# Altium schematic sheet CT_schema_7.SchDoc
size 259 x 245 mm
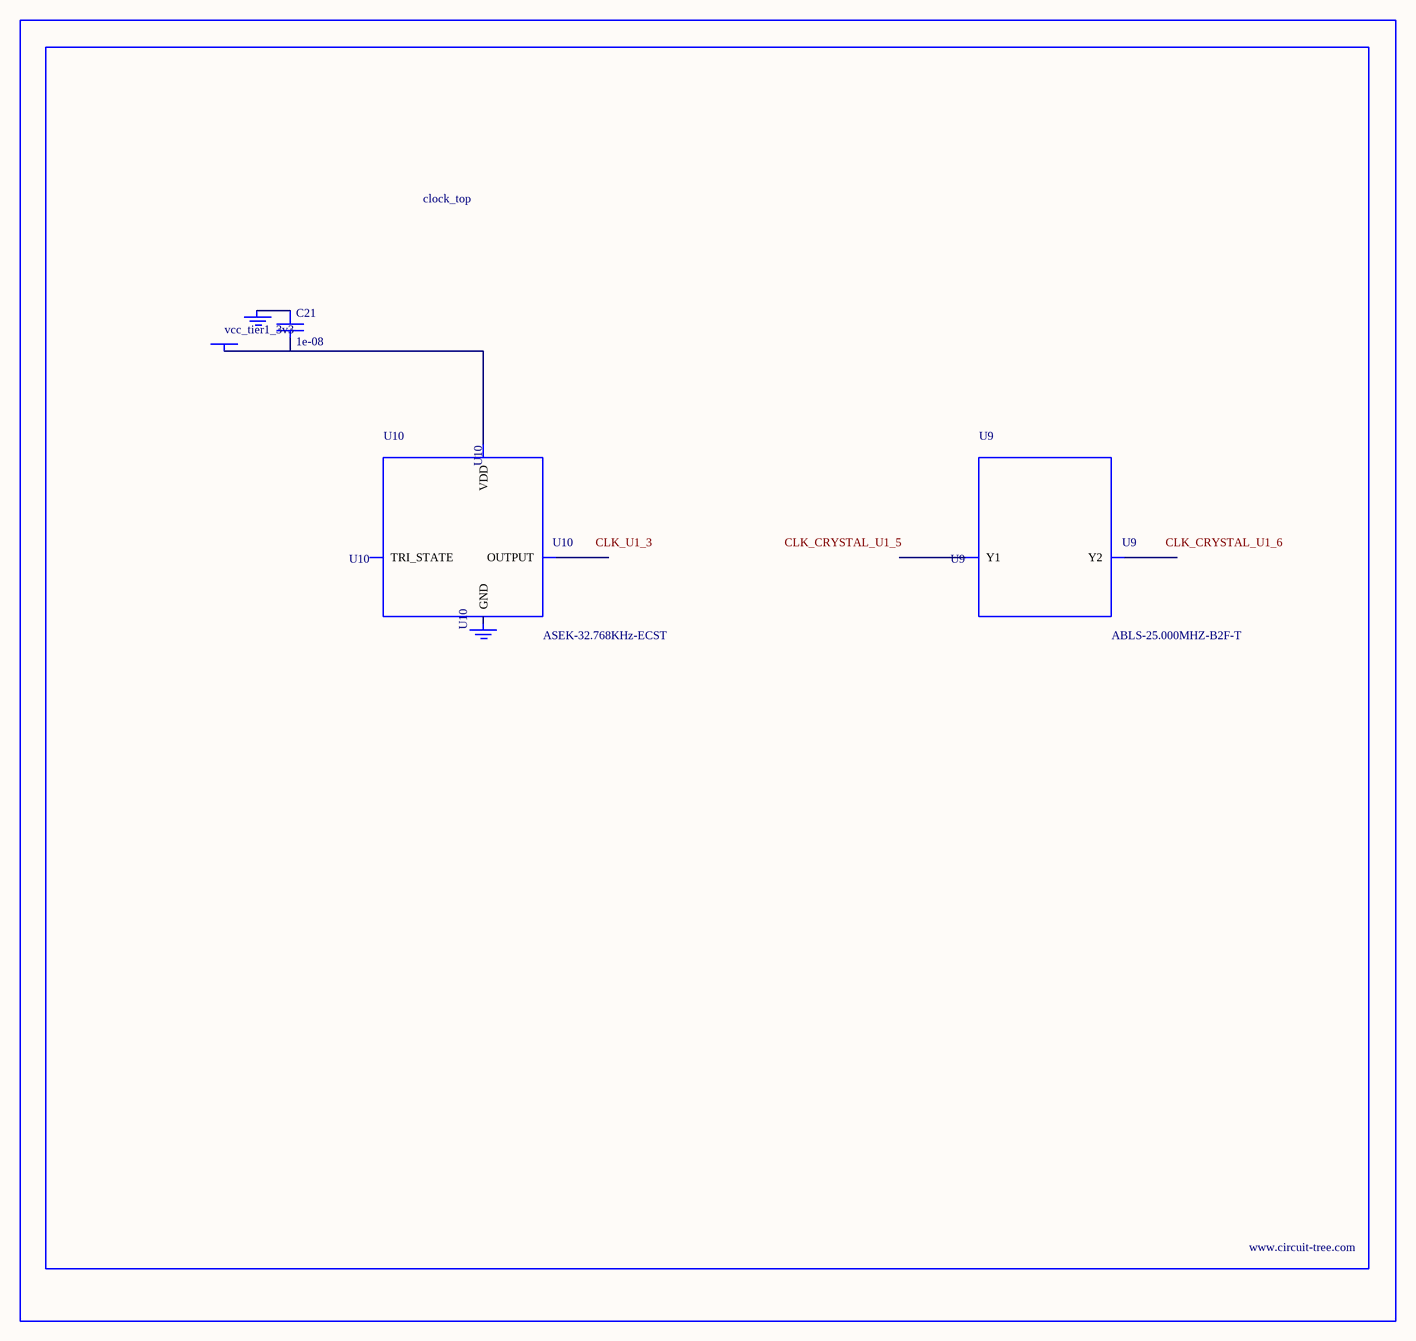
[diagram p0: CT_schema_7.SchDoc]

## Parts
BORDER6  (no value)
C21  1e-08  [C0402]
GND_INSTANCE_6_0  (no value)
GND_INSTANCE_6_1  (no value)
POWER_INSTANCE_6_0  vcc_tier1_3v3
U9  ABLS-25.000MHZ-B2F-T  [ABLS-25.000MHZ-B2F-T]
U10  ASEK-32.768KHz-ECST  [ASEK]

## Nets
NetC21_1: C21.1 GND_INSTANCE_6_0.0(GND)
NetC21_2: C21.2 POWER_INSTANCE_6_0.0(PWR) U10.4(VDD)

Not connected (* = marked no-connect by the designer): GND_INSTANCE_6_1 0(GND); U9 1(Y1) 2(Y2); U10 1(TRI_STATE) 2(GND) 3(OUTPUT)

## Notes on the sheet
- Labels drawn without touching a wire or pin: CLK_CRYSTAL_U1_5, CLK_CRYSTAL_U1_6, CLK_U1_3

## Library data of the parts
BORDER6 = BORDER_PAGE6
C21 = C0402C103K3RAC
GND_INSTANCE_6_0 GND_INSTANCE_6_1 = GND
POWER_INSTANCE_6_0 = PWR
